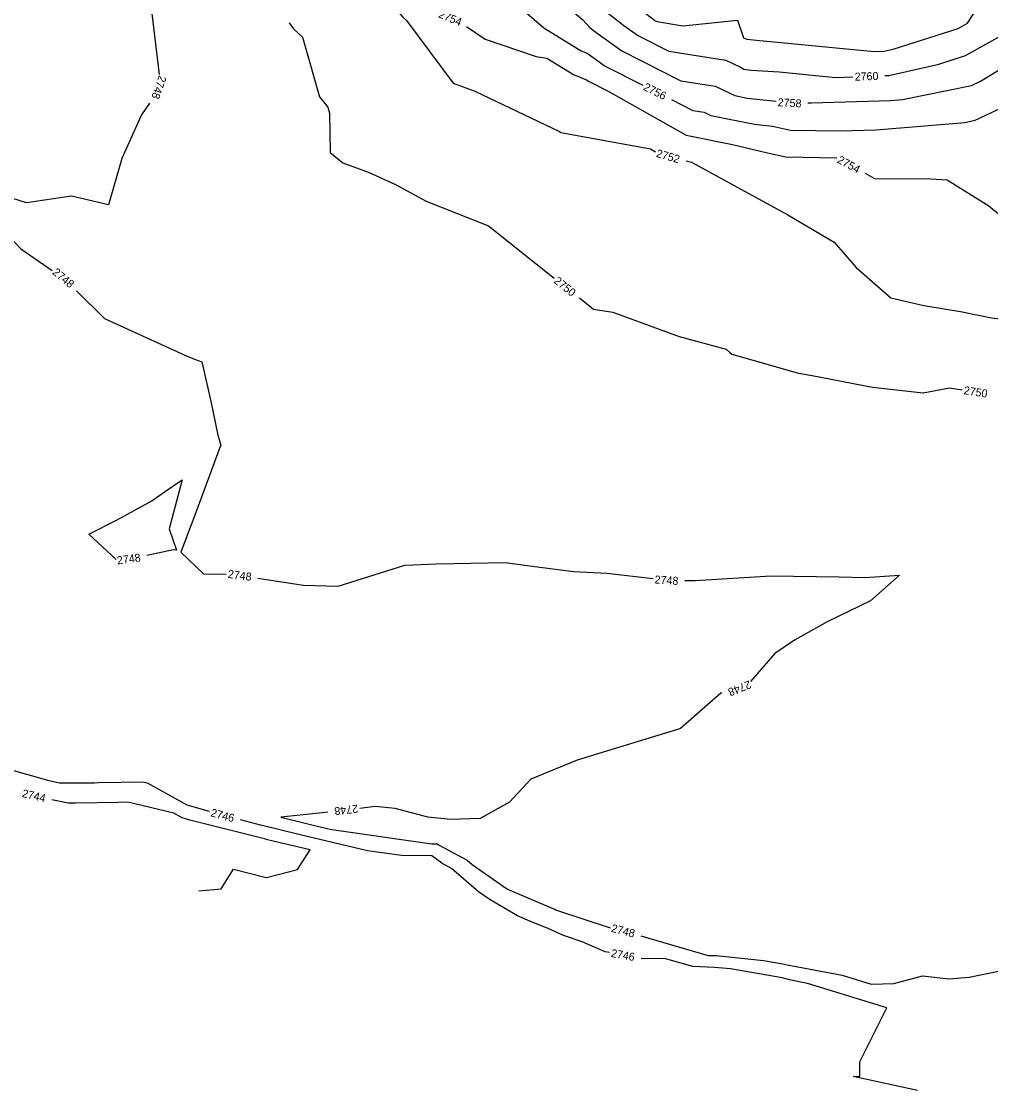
# Model space of a CAD drawing. Extents: x 1326424 to 1329294, y 1001359 to 1003823.
# Drawn here: x 1328279.2 to 1328521.7, y 1001359 to 1001626.3 of the extents above; entities that cross this region are included whole.
import ezdxf

# ---------------------------------------------------------------- set-up
doc = ezdxf.new("R2010")
doc.units = 0
doc.layers.add('Prop Rem of Exist Asph Pvmt', color=7, linetype='Continuous')
doc.layers.add('Scratch_Level_3', color=7, linetype='Continuous')

msp = doc.modelspace()

# ---------------------------------------------------------------- linework, layer by layer
at = {"layer": 'Prop Rem of Exist Asph Pvmt'}
for points in [[(1328401.73, 1001653.66), (1328402.35, 1001653.07), (1328406.22, 1001650.02), (1328408.88, 1001646.89), (1328411.98, 1001643.36), (1328412.53, 1001642.77), (1328413.76, 1001641.72), (1328424.09, 1001629.87), (1328429.96, 1001625.3), (1328433.61, 1001622.68), (1328441.21, 1001618.84), (1328455.43, 1001616.6), (1328459.12, 1001614.84), (1328459.96, 1001614.32), (1328461.78, 1001614.14), (1328468.79, 1001613.66), (1328482.83, 1001612.28), (1328487.21, 1001612.44)], [(1328495.2, 1001612.73), (1328496.2, 1001612.77), (1328508.69, 1001615.6), (1328515.34, 1001617.73), (1328525.51, 1001623.41), (1328529.21, 1001629.1), (1328538.59, 1001636.25), (1328538.99, 1001636.75), (1328540.69, 1001637.36), (1328558.76, 1001642.48), (1328568.33, 1001646.35), (1328575.49, 1001648.63), (1328575.75, 1001648.74), (1328581.33, 1001651.18), (1328584.42, 1001652.93)]]:
    msp.add_lwpolyline(points, dxfattribs=at)
at = {"layer": 'Scratch_Level_3'}
for points in [[(1328277.62, 1001675.77), (1328277.88, 1001675.41), (1328285.42, 1001668.7), (1328286.52, 1001667.89), (1328293.8, 1001660.36), (1328300.96, 1001657.21), (1328306, 1001652.28), (1328325.36, 1001639.86), (1328314.11, 1001639.53), (1328311.03, 1001637.86), (1328311.27, 1001633.2), (1328313.72, 1001613.03)], [(1328358.16, 1001672.23), (1328368.88, 1001664.93), (1328369.55, 1001664.06), (1328378.87, 1001653.49), (1328383.73, 1001646.1), (1328383.94, 1001644.82), (1328385.26, 1001644.41), (1328391.86, 1001638.57), (1328399.98, 1001633.32), (1328400.06, 1001633.24), (1328400.09, 1001633.21), (1328400.24, 1001633.09), (1328409.92, 1001624.65), (1328419.29, 1001618.97), (1328420.74, 1001618.37), (1328425.26, 1001615.12), (1328434.68, 1001610.35)], [(1328385.79, 1001655.6), (1328387.79, 1001652.61), (1328390.98, 1001648.88), (1328391.14, 1001647.99), (1328394.04, 1001647.07), (1328396.46, 1001647.78), (1328400.2, 1001644.23), (1328403, 1001641.52), (1328406.31, 1001637.99), (1328419.66, 1001626.71), (1328421.38, 1001624.74), (1328422.36, 1001623.98), (1328429.44, 1001618.9), (1328444.18, 1001611.44), (1328452.73, 1001610.09), (1328457.65, 1001607.75), (1328460.75, 1001607.12), (1328468.01, 1001606.34)], [(1328354.62, 1001642.66), (1328359.61, 1001637.96), (1328371.19, 1001630.66), (1328374.08, 1001628.01), (1328374.66, 1001627.32), (1328375.56, 1001626.56), (1328387.21, 1001610.88), (1328392.62, 1001608.89), (1328413.84, 1001598.81), (1328414.18, 1001598.5), (1328436.59, 1001594.4), (1328437.83, 1001593.7)], [(1328427.85, 1001634.19), (1328437.57, 1001626.62), (1328437.79, 1001626.47), (1328438.23, 1001626.24), (1328444.69, 1001625.22), (1328458.31, 1001626.58), (1328459.85, 1001622.18), (1328460.68, 1001621.87), (1328464.7, 1001621.47), (1328464.89, 1001621.45), (1328492.56, 1001618.75), (1328495.01, 1001618.83), (1328497.31, 1001619.35), (1328513.57, 1001624.56), (1328515.9, 1001625.86), (1328518.38, 1001629.68)], [(1328475.98, 1001605.92), (1328476.83, 1001605.95), (1328496.63, 1001606.51), (1328499.64, 1001606.76), (1328516.85, 1001610.31), (1328519.12, 1001611.39), (1328533.82, 1001620.24), (1328535.13, 1001620.97), (1328535.23, 1001621.12), (1328535.52, 1001621.34), (1328547.46, 1001624.89), (1328549.2, 1001625.35), (1328550.21, 1001625.65), (1328571.18, 1001631.29)], [(1328346.19, 1001625.97), (1328347.26, 1001624.45), (1328349.54, 1001622.32), (1328350.06, 1001620.59), (1328353.84, 1001607.41), (1328355.88, 1001604.83), (1328356.27, 1001603.38), (1328356.47, 1001593.49), (1328359.65, 1001590.94), (1328366.21, 1001588.51), (1328372.83, 1001585.53), (1328380.49, 1001581.38), (1328395.63, 1001575.39), (1328395.8, 1001575.28), (1328396.04, 1001575.19), (1328412.53, 1001562.13)], [(1328390.59, 1001625.06), (1328395.21, 1001621.84), (1328407.98, 1001617.49), (1328410.63, 1001617.12), (1328417.36, 1001613.04), (1328420.61, 1001611.68), (1328421.09, 1001611.34), (1328425.99, 1001608.86), (1328445.5, 1001597.87), (1328445.93, 1001597.77), (1328457.1, 1001595.52), (1328465.83, 1001593.42), (1328470.44, 1001592.42), (1328483.15, 1001592.23), (1328483.23, 1001592.19)], [(1328311.26, 1001605.89), (1328309.32, 1001602.97), (1328304.36, 1001592.02), (1328301.05, 1001580.41), (1328291.74, 1001582.64), (1328280.5, 1001580.97), (1328264.2, 1001586.08), (1328262.85, 1001586.34), (1328263.48, 1001585.52), (1328264.08, 1001585.19), (1328279.09, 1001569.43), (1328286.95, 1001564.06)], [(1328441.82, 1001606.74), (1328447.16, 1001604.04), (1328450.02, 1001603.59), (1328451.67, 1001602.8), (1328462.59, 1001600.6), (1328467.1, 1001600.1), (1328471.64, 1001599.12), (1328484.13, 1001598.94), (1328493.06, 1001599.19), (1328515.22, 1001601.04), (1328517.77, 1001601.57), (1328524.73, 1001604.87), (1328526.82, 1001604.9), (1328528.65, 1001604.78), (1328539.64, 1001603.46)], [(1328445.47, 1001591.48), (1328446.88, 1001591.14), (1328462.84, 1001582.35), (1328470.97, 1001577.95), (1328482.5, 1001571.09), (1328488.02, 1001564.79), (1328496.72, 1001557.23), (1328504.94, 1001555.26), (1328514.11, 1001553.77), (1328521.84, 1001552.23), (1328525.35, 1001551.81), (1328533.89, 1001550.78)], [(1328490.24, 1001588.33), (1328492.63, 1001587.02), (1328506.73, 1001586.94), (1328510.81, 1001586.67), (1328521.18, 1001580.16), (1328524.16, 1001577.81), (1328525.87, 1001576.49), (1328534.22, 1001572.25), (1328557.15, 1001574.14), (1328561.56, 1001574.14), (1328568.88, 1001574.75), (1328585.05, 1001579.15)], [(1328293.06, 1001558.95), (1328300.05, 1001552.02), (1328320.16, 1001542.84), (1328322.52, 1001541.89), (1328324.37, 1001541.22), (1328326.72, 1001530.95), (1328328.34, 1001522.86), (1328329.12, 1001520.38), (1328328.88, 1001519.75), (1328322.89, 1001503.53), (1328319.09, 1001493.64), (1328324.75, 1001488.19), (1328330.49, 1001488.14)], [(1328418.8, 1001557.16), (1328422.3, 1001554.39), (1328427.16, 1001553.59), (1328443.73, 1001547.56), (1328455.48, 1001544.36), (1328456.47, 1001543.55), (1328456.91, 1001543.11), (1328473.63, 1001538.35), (1328477.05, 1001537.81), (1328492.13, 1001534.9), (1328504.8, 1001533.42), (1328511.39, 1001534.7), (1328514.57, 1001534.2)], [(1328311.83, 1001506.48), (1328315.04, 1001508.67), (1328319.45, 1001511.67), (1328316.2, 1001499.47), (1328318, 1001494.08), (1328317.32, 1001494.2), (1328310.62, 1001492.81)], [(1328302.94, 1001491.78), (1328296.15, 1001498.1), (1328303.07, 1001501.58), (1328311.83, 1001506.48)], [(1328338.41, 1001487.13), (1328349.8, 1001485.36), (1328358.48, 1001485.13), (1328375.14, 1001490.39), (1328383.03, 1001490.7), (1328400.23, 1001490.99), (1328408.94, 1001489.86), (1328417.42, 1001488.79), (1328425.7, 1001488.36), (1328437.22, 1001487.03)], [(1328445.19, 1001486.5), (1328447.77, 1001486.53), (1328466.66, 1001487.71), (1328483.78, 1001487.42), (1328490.22, 1001487.27), (1328498.86, 1001487.83), (1328491.65, 1001481.43), (1328480.76, 1001476.18), (1328472.64, 1001471.59), (1328467.7, 1001468.26), (1328461.6, 1001461.3)], [(1328454.43, 1001458.44), (1328454.14, 1001458.38), (1328444.11, 1001449.5), (1328443.36, 1001449.26), (1328425.55, 1001443.86), (1328418.23, 1001441.62), (1328406.68, 1001436.9), (1328401.34, 1001431.13), (1328394.02, 1001427.02), (1328386.56, 1001426.8), (1328380.93, 1001427.36), (1328372.74, 1001429.51), (1328367.69, 1001430.01), (1328363.87, 1001429.55)], [(1328326.3, 1001428.76), (1328320.69, 1001430.36), (1328310.99, 1001435.8), (1328309.79, 1001436.08), (1328298.61, 1001435.92), (1328297.55, 1001435.9), (1328288.79, 1001435.91), (1328286.17, 1001436.48), (1328275.03, 1001439.59), (1328270.64, 1001440.74), (1328251.22, 1001456.69), (1328243.73, 1001456.84), (1328234.34, 1001457.32)], [(1328323.64, 1001408.99), (1328329.25, 1001409.47), (1328332.3, 1001414.38), (1328340.48, 1001412.3), (1328340.51, 1001412.32), (1328348.26, 1001414.28), (1328351.44, 1001419.19), (1328342.55, 1001421.3), (1328340.44, 1001421.82), (1328340.37, 1001421.84), (1328321.41, 1001426.66), (1328319.44, 1001427.23), (1328317.35, 1001428.4), (1328305.86, 1001431.08), (1328303.45, 1001431.05), (1328292.84, 1001430.84), (1328290.95, 1001430.84), (1328286.88, 1001431.74)], [(1328426.37, 1001393.52), (1328425.26, 1001393.72), (1328419.52, 1001396.24), (1328414.79, 1001397.82), (1328411, 1001399.51), (1328407.03, 1001401.15), (1328403.36, 1001402.68), (1328396.49, 1001406.69), (1328393.6, 1001408.71), (1328386.84, 1001414.54), (1328384.44, 1001415.83), (1328381.9, 1001417.74), (1328374.29, 1001417.76), (1328365.82, 1001418.95), (1328348.93, 1001422.97), (1328339.09, 1001425.39), (1328339.05, 1001425.4), (1328334.02, 1001426.68)], [(1328355.92, 1001428.61), (1328353.69, 1001428.35), (1328344.14, 1001427.39), (1328355.3, 1001424.64), (1328356.89, 1001424.26), (1328381.86, 1001420.74), (1328383.25, 1001420.74), (1328383.72, 1001420.39), (1328390.77, 1001416.6), (1328392.01, 1001415.53), (1328400.55, 1001409.58), (1328401.37, 1001409.1), (1328412.17, 1001404.56), (1328412.64, 1001404.37), (1328413.1, 1001404.16), (1328426.47, 1001399.69)], [(1328434.17, 1001397.71), (1328450.99, 1001392.82), (1328453.09, 1001392.75), (1328464.86, 1001391.55), (1328469.66, 1001390.73), (1328470.35, 1001390.53), (1328484.54, 1001387.87), (1328491.77, 1001385.65), (1328497.43, 1001385.79), (1328504.6, 1001387.71), (1328511.29, 1001386.98), (1328516.27, 1001387.37), (1328528.16, 1001389.83), (1328532.1, 1001390.61)], [(1328503.38, 1001359.01), (1328487.26, 1001362.58), (1328488.94, 1001362.62), (1328488.92, 1001366.19), (1328495.74, 1001379.72), (1328475.89, 1001385.83), (1328471.38, 1001386.68), (1328469.51, 1001387.21), (1328456.6, 1001389.42), (1328452.61, 1001389.82), (1328447.14, 1001390), (1328440.13, 1001392.04), (1328434.75, 1001391.99), (1328434.24, 1001392.08)]]:
    msp.add_lwpolyline(points, dxfattribs=at)

# ---------------------------------------------------------------- texts
at = {"layer": 'Prop Rem of Exist Asph Pvmt'}
msp.add_text('2760', height=2, rotation=2.0863, dxfattribs=at).set_placement((1328487.68, 1001611.46))
at = {"layer": 'Scratch_Level_3'}
for s, rotation, p in [('2754', 337.3401, (1328383.4, 1001627.37)), ('2748', 250.9574, (1328313.69, 1001612.94)), ('2756', 333.1521, (1328434.6, 1001609.27)), ('2758', 357.039, (1328468.35, 1001605.09)), ('2752', 343.8124, (1328437.86, 1001592.46)), ('2754', 331.1778, (1328483.11, 1001591.11)), ('2748', 320.1815, (1328286.83, 1001563.3)), ('2750', 321.6217, (1328412.24, 1001561.08)), ('2750', 351.007, (1328514.83, 1001533.14)), ('2748', 7.7032, (1328303.28, 1001490.53)), ('2748', 352.715, (1328330.78, 1001487.2)), ('2748', 356.1757, (1328437.56, 1001485.81)), ('2748', 201.7046, (1328461.29, 1001461.6)), ('2744', 346.6836, (1328279.25, 1001432.45)), ('2746', 344.9625, (1328326.43, 1001427.63)), ('2748', 186.7611, (1328363.33, 1001430.5)), ('2748', 345.6111, (1328426.61, 1001398.75)), ('2746', 349.6768, (1328426.6, 1001392.46))]:
    msp.add_text(s, height=2, rotation=rotation, dxfattribs=at).set_placement(p)

doc.saveas('drawing.dxf')
